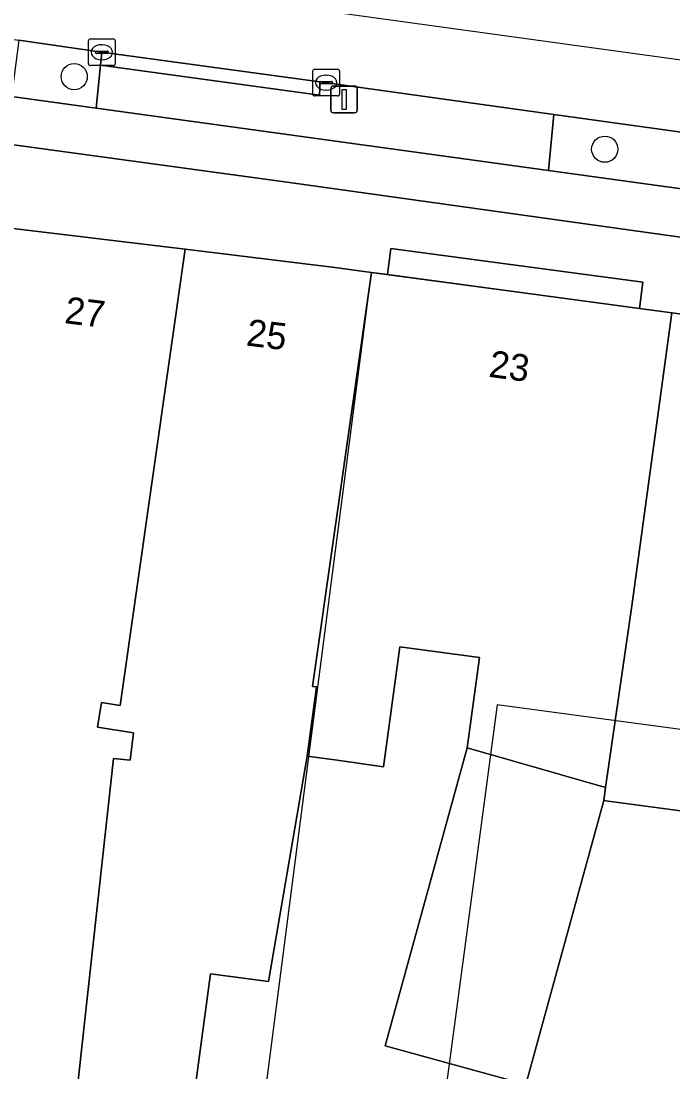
# Model space of a CAD drawing. Extents: x 160663 to 161506, y 382245 to 383291.
# Drawn here: x 160988.28 to 161012.63, y 383209.32 to 383248.56 of the extents above; entities that cross this region are included whole.
import ezdxf

# ---------------------------------------------------------------- set-up
doc = ezdxf.new("R2010")
doc.units = 0
for name, color, linetype in [('IMGEO_Berm_open', 7, 'Continuous'), ('IMGEO_Boom', 7, 'Continuous'), ('IMGEO_Erf', 7, 'Continuous'), ('IMGEO_Fietspad_gesloten', 7, 'Continuous'), ('IMGEO_Groenvoorziening', 7, 'Continuous'), ('IMGEO_Kolk', 7, 'Continuous'), ('IMGEO_Lichtmast', 7, 'Continuous'), ('IMGEO_Pand', 7, 'Continuous'), ('IMGEO_Pand_nummerreeks', 7, 'Continuous'), ('IMGEO_Pand_vergunning_verleend', 7, 'Continuous'), ('IMGEO_Rijbaan_lokaal_gesloten', 7, 'Continuous'), ('IMGEO_Voetpad_open', 7, 'Continuous')]:
    doc.layers.add(name, color=color, linetype=linetype)

msp = doc.modelspace()

# ---------------------------------------------------------------- linework, layer by layer
at = {"layer": 'IMGEO_Berm_open'}
msp.add_lwpolyline([(160999.446, 383246.282), (160999.438, 383246.043), (160999.43, 383245.785), (160991.255, 383246.905), (160991.087, 383245.306), (161007.978, 383242.975), (161008.184, 383245.068)], close=True, dxfattribs=at)
at = {"layer": 'IMGEO_Boom'}
for centre in [(160990.27, 383246.482), (161010.085, 383243.774)]:
    msp.add_circle(centre, 0.489, dxfattribs=at)
at = {"layer": 'IMGEO_Erf'}
for points in [[(161006.859, 383208.935), (161001.885, 383210.303), (161004.95, 383221.423), (161005.403, 383224.79), (161002.428, 383225.189), (161001.826, 383220.711), (161000, 383220.97), (160998.968, 383221.116), (160998.509, 383218.429), (160997.531, 383212.695), (160995.356, 383212.988), (160993.199, 383196.925)], [(161013.753, 383208.642), (161015.536, 383215.037), (161020.579, 383214.359), (161021.506, 383221.255), (161017.421, 383221.804), (161017.568, 383222.896), (161017.343, 383222.926), (161013.786, 383223.405), (161013.198, 383219.032), (161010.588, 383219.382), (161010.207, 383219.433), (161010.049, 383219.455), (161007.135, 383208.859)]]:
    msp.add_lwpolyline(points, dxfattribs=at)
at = {"layer": 'IMGEO_Fietspad_gesloten'}
for points in [[(160749.571, 383275.838), (160772.375, 383273.271), (160826.897, 383266.189), (160865.807, 383260.226), (160871.952, 383259.299), (160876.01, 383258.649), (160907.21, 383254.866), (160915.937, 383253.784), (160972.356, 383246.078), (160977.609, 383245.36), (160998.315, 383242.532), (161054.596, 383234.67)], [(161048.826, 383237.337), (161033.753, 383239.417), (161030.202, 383239.907), (161012.954, 383242.288), (161007.978, 383242.975), (160991.087, 383245.306), (160987.927, 383245.742), (160977.584, 383247.17), (160972.582, 383247.922), (160970.219, 383248.244), (160948.513, 383251.198), (160944.615, 383251.729), (160929.927, 383253.728), (160926.09, 383254.25), (160916.951, 383255.494), (160906.447, 383256.836), (160882.483, 383259.669), (160873.765, 383260.871), (160866.022, 383262.062), (160855.96, 383263.61), (160850.573, 383264.439)]]:
    msp.add_lwpolyline(points, dxfattribs=at)
at = {"layer": 'IMGEO_Groenvoorziening'}
for points in [[(160991.255, 383246.905), (160991.289, 383247.261), (160991.302, 383247.393), (160988.207, 383247.841), (160987.927, 383245.742), (160991.087, 383245.306)], [(161013.209, 383244.37), (161008.184, 383245.068), (161007.978, 383242.975), (161012.954, 383242.288)]]:
    msp.add_lwpolyline(points, close=True, dxfattribs=at)
at = {"layer": 'IMGEO_Kolk'}
for p, q in [((160990.801, 383246.967), (160990.801, 383247.819)), ((160990.876, 383247.893), (160991.728, 383247.893)), ((160991.289, 383247.673), (160991.314, 383247.673)), ((160991.802, 383247.819), (160991.802, 383246.967)), ((160991.06, 383247.387), (160991.06, 383247.399)), ((160991.498, 383247.35), (160991.1, 383247.35)), ((160991.103, 383247.436), (160991.501, 383247.436)), ((160991.544, 383247.399), (160991.544, 383247.387)), ((160991.728, 383246.893), (160990.876, 383246.893)), ((160991.312, 383247.113), (160991.287, 383247.113)), ((160999.255, 383246.76), (161000.107, 383246.76)), ((160999.18, 383245.834), (160999.18, 383246.686)), ((160999.668, 383246.54), (160999.693, 383246.54)), ((161000.181, 383246.686), (161000.181, 383245.834)), ((160999.439, 383246.254), (160999.439, 383246.266)), ((160999.877, 383246.217), (160999.479, 383246.217)), ((160999.482, 383246.303), (160999.88, 383246.303)), ((160999.691, 383245.98), (160999.666, 383245.98)), ((160999.923, 383246.266), (160999.923, 383246.254)), ((161000.107, 383245.76), (160999.255, 383245.76))]:
    msp.add_line(p, q, dxfattribs=at)
for points in [[(160990.801, 383246.967), (160990.801, 383247.819)], [(160990.876, 383247.893), (160991.728, 383247.893)], [(160991.802, 383247.819), (160991.802, 383246.967)], [(160991.728, 383246.893), (160990.876, 383246.893)], [(160999.255, 383246.76), (161000.107, 383246.76)], [(160999.18, 383245.834), (160999.18, 383246.686)], [(161000.181, 383246.686), (161000.181, 383245.834)], [(161000.107, 383245.76), (160999.255, 383245.76)]]:
    msp.add_lwpolyline(points, dxfattribs=at)
for centre, radius, start, end in [((160990.878, 383247.817), 0.0765, 91.552, 178.448), ((160990.878, 383247.817), 0.0765, 91.552, 178.448), ((160991.726, 383247.817), 0.0765, 1.552, 88.448), ((160991.726, 383247.817), 0.0765, 1.552, 88.448), ((160991.1, 383247.396), 0.0403, 85.8775, 175.7526), ((160991.097, 383247.386), 0.0366, 178.938, 274.7102), ((160991.501, 383247.393), 0.043, 264.8664, 352.4533), ((160991.505, 383247.398), 0.0386, 1.7309, 96.639), ((160990.878, 383246.969), 0.0765, 181.552, 268.448), ((160990.878, 383246.969), 0.0765, 181.552, 268.448), ((160991.726, 383246.969), 0.0765, 271.552, 358.448), ((160991.726, 383246.969), 0.0765, 271.552, 358.448), ((160999.257, 383246.684), 0.0765, 91.552, 178.448), ((160999.257, 383246.684), 0.0765, 91.552, 178.448), ((161000.105, 383246.684), 0.0765, 1.552, 88.448), ((161000.105, 383246.684), 0.0765, 1.552, 88.448), ((160999.479, 383246.263), 0.0403, 85.8775, 175.7526), ((160999.476, 383246.253), 0.0366, 178.938, 274.7102), ((160999.88, 383246.26), 0.043, 264.8664, 352.4533), ((160999.884, 383246.265), 0.0386, 1.7309, 96.639), ((160999.257, 383245.836), 0.0765, 181.552, 268.448), ((160999.257, 383245.836), 0.0765, 181.552, 268.448), ((161000.105, 383245.836), 0.0765, 271.552, 358.448), ((161000.105, 383245.836), 0.0765, 271.552, 358.448)]:
    msp.add_arc(centre, radius, start, end, dxfattribs=at)
for centre, major_axis, ratio, start_param, end_param in [((160991.288, 383247.393), (-0.387, 0.002), 0.722429, 4.712389, 7.853982), ((160991.313, 383247.393), (-0.39, 0.002), 0.717154, 1.570796, 4.712389), ((160999.667, 383246.26), (-0.387, 0.002), 0.722429, 4.712389, 7.853982), ((160999.692, 383246.26), (-0.39, 0.002), 0.717154, 1.570796, 4.712389)]:
    msp.add_ellipse(centre, major_axis=major_axis, ratio=ratio, start_param=start_param, end_param=end_param, dxfattribs=at)
at = {"layer": 'IMGEO_Lichtmast'}
for p, q in [((160999.852, 383245.23), (160999.852, 383246.03)), ((160999.852, 383246.03), (160999.852, 383245.23)), ((160999.952, 383246.13), (161000.742, 383246.13)), ((161000.742, 383246.13), (160999.952, 383246.13)), ((161000.842, 383246.03), (161000.842, 383245.23)), ((161000.842, 383245.23), (161000.842, 383246.03)), ((161000.742, 383245.13), (160999.952, 383245.13)), ((160999.952, 383245.13), (161000.742, 383245.13))]:
    msp.add_line(p, q, dxfattribs=at)
msp.add_lwpolyline([(161000.272, 383246.005), (161000.422, 383246.005), (161000.422, 383245.255), (161000.272, 383245.255), (161000.272, 383246.005)], dxfattribs=at)
for centre, start, end in [((160999.952, 383246.03), 90, 180), ((160999.952, 383246.03), 90, 180), ((161000.742, 383246.03), 0, 90), ((161000.742, 383246.03), 360, 90), ((160999.952, 383245.23), 180, 270), ((160999.952, 383245.23), 180, 270), ((161000.742, 383245.23), 270, 0), ((161000.742, 383245.23), 270, 0)]:
    msp.add_arc(centre, 0.1, start, end, dxfattribs=at)
at = {"layer": 'IMGEO_Pand'}
for points in [[(160991.733, 383221.027), (160992.361, 383220.968), (160992.489, 383221.987), (160991.144, 383222.191), (160991.285, 383223.122), (160991.989, 383223.002), (160994.411, 383240.035), (160987.783, 383240.842), (160987.806, 383241.015), (160987.706, 383241.028), (160985.263, 383224.635), (160983.434, 383209.525), (160982.349, 383201.177), (160981.134, 383192.067), (160988.36, 383190.705), (160988.738, 383193.679)], [(160998.968, 383221.116), (160999.315, 383223.699), (160999.166, 383223.719), (161000, 383229.568), (161001.369, 383239.171), (161000, 383239.354), (160994.411, 383240.035), (160991.989, 383223.002), (160991.285, 383223.122), (160991.144, 383222.191), (160992.489, 383221.987), (160992.361, 383220.968), (160991.733, 383221.027), (160988.738, 383193.679), (160988.36, 383190.705), (160994.345, 383189.577), (160995.294, 383196.643), (160993.199, 383196.925), (160995.356, 383212.988), (160997.531, 383212.695), (160998.509, 383218.429)], [(161010.119, 383219.942), (161011.106, 383226.811), (161012.588, 383237.67), (161011.383, 383237.831), (161001.967, 383239.091), (161001.369, 383239.171), (161000, 383229.568), (160999.166, 383223.719), (160999.315, 383223.699), (160998.968, 383221.116), (161000, 383220.97), (161001.826, 383220.711), (161002.428, 383225.189), (161005.403, 383224.79), (161004.95, 383221.423)], [(161019.54, 383236.74), (161012.588, 383237.67), (161011.106, 383226.811), (161010.119, 383219.942), (161010.049, 383219.455), (161010.207, 383219.433), (161010.588, 383219.382), (161013.198, 383219.032), (161013.786, 383223.405), (161017.343, 383222.926)], [(161010.049, 383219.455), (161010.119, 383219.942), (161004.95, 383221.423), (161001.885, 383210.303), (161006.859, 383208.935), (161007.075, 383208.875), (161007.135, 383208.859)]]:
    msp.add_lwpolyline(points, close=True, dxfattribs=at)
at = {"layer": 'IMGEO_Pand_vergunning_verleend'}
msp.add_lwpolyline([(160997.115, 383206.28), (161001.369, 383239.171), (161019.133, 383236.794), (161017.087, 383221.549), (161006.072, 383223.027), (161003.485, 383203.75)], close=True, dxfattribs=at)
at = {"layer": 'IMGEO_Rijbaan_lokaal_gesloten'}
msp.add_lwpolyline([(161038.265, 383243.607), (160926.374, 383259.023), (160926.118, 383256.999), (160926.07, 383256.622), (160926.395, 383256.579), (160930.26, 383256.062), (160941.434, 383254.466), (160944.887, 383253.96), (160947.814, 383253.531), (160970.494, 383250.343), (160971.748, 383250.181), (160972.88, 383250.034), (160977.884, 383249.337), (160988.207, 383247.841), (160991.302, 383247.393), (160999.446, 383246.282), (161008.184, 383245.068), (161013.209, 383244.37), (161020.794, 383243.317), (161030.482, 383241.923), (161034.004, 383241.447), (161038.92, 383240.782)], dxfattribs=at)
at = {"layer": 'IMGEO_Voetpad_open'}
for points in [[(160998.315, 383242.532), (160977.609, 383245.36), (160972.356, 383246.078), (160915.937, 383253.784)], [(161054.596, 383234.67), (160998.315, 383242.532)], [(160987.783, 383240.842), (160994.411, 383240.035), (161000, 383239.354), (161001.369, 383239.171), (161001.967, 383239.091), (161002.097, 383240.063), (161011.513, 383238.803), (161011.383, 383237.831), (161012.588, 383237.67), (161019.54, 383236.74), (161019.629, 383237.405), (161028.421, 383236.228), (161028.332, 383235.563), (161029.172, 383235.45), (161029.57, 383235.397), (161029.622, 383235.271), (161035.971, 383234.418), (161036.09, 383234.572), (161036.914, 383234.459), (161048.179, 383232.914)]]:
    msp.add_lwpolyline(points, dxfattribs=at)
for points in [[(160999.446, 383246.282), (160991.302, 383247.393), (160991.289, 383247.261), (160991.255, 383246.905), (160999.43, 383245.785), (160999.438, 383246.043)], [(161011.383, 383237.831), (161011.513, 383238.803), (161002.097, 383240.063), (161001.967, 383239.091)]]:
    msp.add_lwpolyline(points, close=True, dxfattribs=at)

# ---------------------------------------------------------------- texts
at = {"layer": 'IMGEO_Pand_nummerreeks'}
for s, rotation, p in [('27', 353.0558, (160989.879, 383237.282)), ('25', 352.924, (160996.665, 383236.449)), ('23', 352.3781, (161005.724, 383235.279))]:
    msp.add_text(s, height=1, rotation=rotation, dxfattribs=at).set_placement(p)

doc.saveas('drawing.dxf')
